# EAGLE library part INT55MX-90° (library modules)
CT (04/03/2008): make pin numbers visible to make it easier for debug change label of name and value to the correct layers CT (05/03/2008) changing name to int55mx-90°
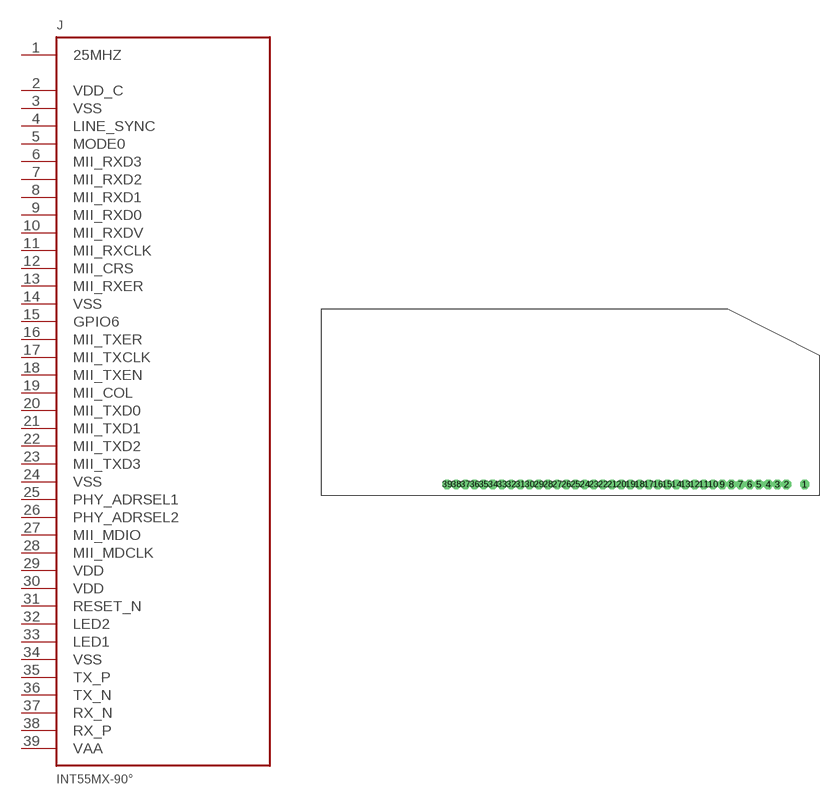
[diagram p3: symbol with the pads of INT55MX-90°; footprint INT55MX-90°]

Designator prefix J

## INT55MX-90°  [INT55MX-90°]
1  25MHZ
2  VDD_C
3  VSS
4  LINE_SYNC
5  MODE0
6  MII_RXD3
7  MII_RXD2
8  MII_RXD1
9  MII_RXD0
10  MII_RXDV
11  MII_RXCLK
12  MII_CRS
13  MII_RXER
14  VSS
15  GPIO6
16  MII_TXER
17  MII_TXCLK
18  MII_TXEN
19  MII_COL
20  MII_TXD0
21  MII_TXD1
22  MII_TXD2
23  MII_TXD3
24  VSS
25  PHY_ADRSEL1
26  PHY_ADRSEL2
27  MII_MDIO
28  MII_MDCLK
29  VDD
30  VDD
31  RESET_N
32  LED2
33  LED1
34  VSS
35  TX_P
36  TX_N
37  RX_N
38  RX_P
39  VAA

## Footprint INT55MX-90° (pad centres in mm)
CT (04/03/2008): changed pin numbers p$n to n CT (05/03/2008): changed name to int55mx-90°
drill 0.8 octagon: 1 -2.064,1.553; 2 -4.604,1.553; 3 -5.874,1.553; 4 -7.144,1.553; 5 -8.414,1.553; 6 -9.694,1.553; 7 -10.964,1.553; 8 -12.234,1.553; 9 -13.504,1.553; 10 -14.774,1.553; 11 -16.044,1.553; 12 -17.314,1.553; 13 -18.584,1.553; 14 -19.854,1.553; 15 -21.124,1.553; 16 -22.394,1.553; 17 -23.664,1.553; 18 -24.944,1.553; 19 -26.214,1.553; 20 -27.484,1.553; 21 -28.754,1.553; 22 -30.024,1.553; 23 -31.294,1.553; 24 -32.564,1.553; 25 -33.834,1.553; 26 -35.104,1.553; 27 -36.374,1.553; 28 -37.644,1.553; 29 -38.914,1.553; 30 -40.194,1.553; 31 -41.464,1.553; 32 -42.734,1.553; 33 -44.004,1.553; 34 -45.274,1.553; 35 -46.544,1.553; 36 -47.814,1.553; 37 -49.084,1.553; 38 -50.354,1.553; 39 -51.624,1.553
